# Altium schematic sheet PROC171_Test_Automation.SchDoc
size 431 x 279 mm; Date: Not shown in title block; ApprovedBy: Not shown in title block; CheckedBy: Not shown in title block; Author: Not shown in title block; CompanyName: Not shown in title block; Engineer: Not shown in title block; Organization: Not shown in title block; Address1: Not shown in title block; Address2: Not shown in title block; Address3: Not shown in title block; Address4: Not shown in title block; DocumentNumber: 14; Revision: Use project parameter SCH_Rev; SheetNumber: 14; SheetTotal: 26; PageSetup: Record=PageOptions¦CenterHorizontal=True¦CenterVertical=True¦PrintScale=1.00¦XCorrection=1.00¦YCorrection=1.00¦PrintKind=0¦BorderSize=5000000¦LeftOffset=0¦BottomOffset=0¦Orientation=2¦PaperLength=1000¦PaperWidth=1000¦Scale=100¦PaperSource=15¦PrintQuality=600¦MediaType=1¦DitherType=10¦PaperKind=Letter¦PrintScaleMode=1
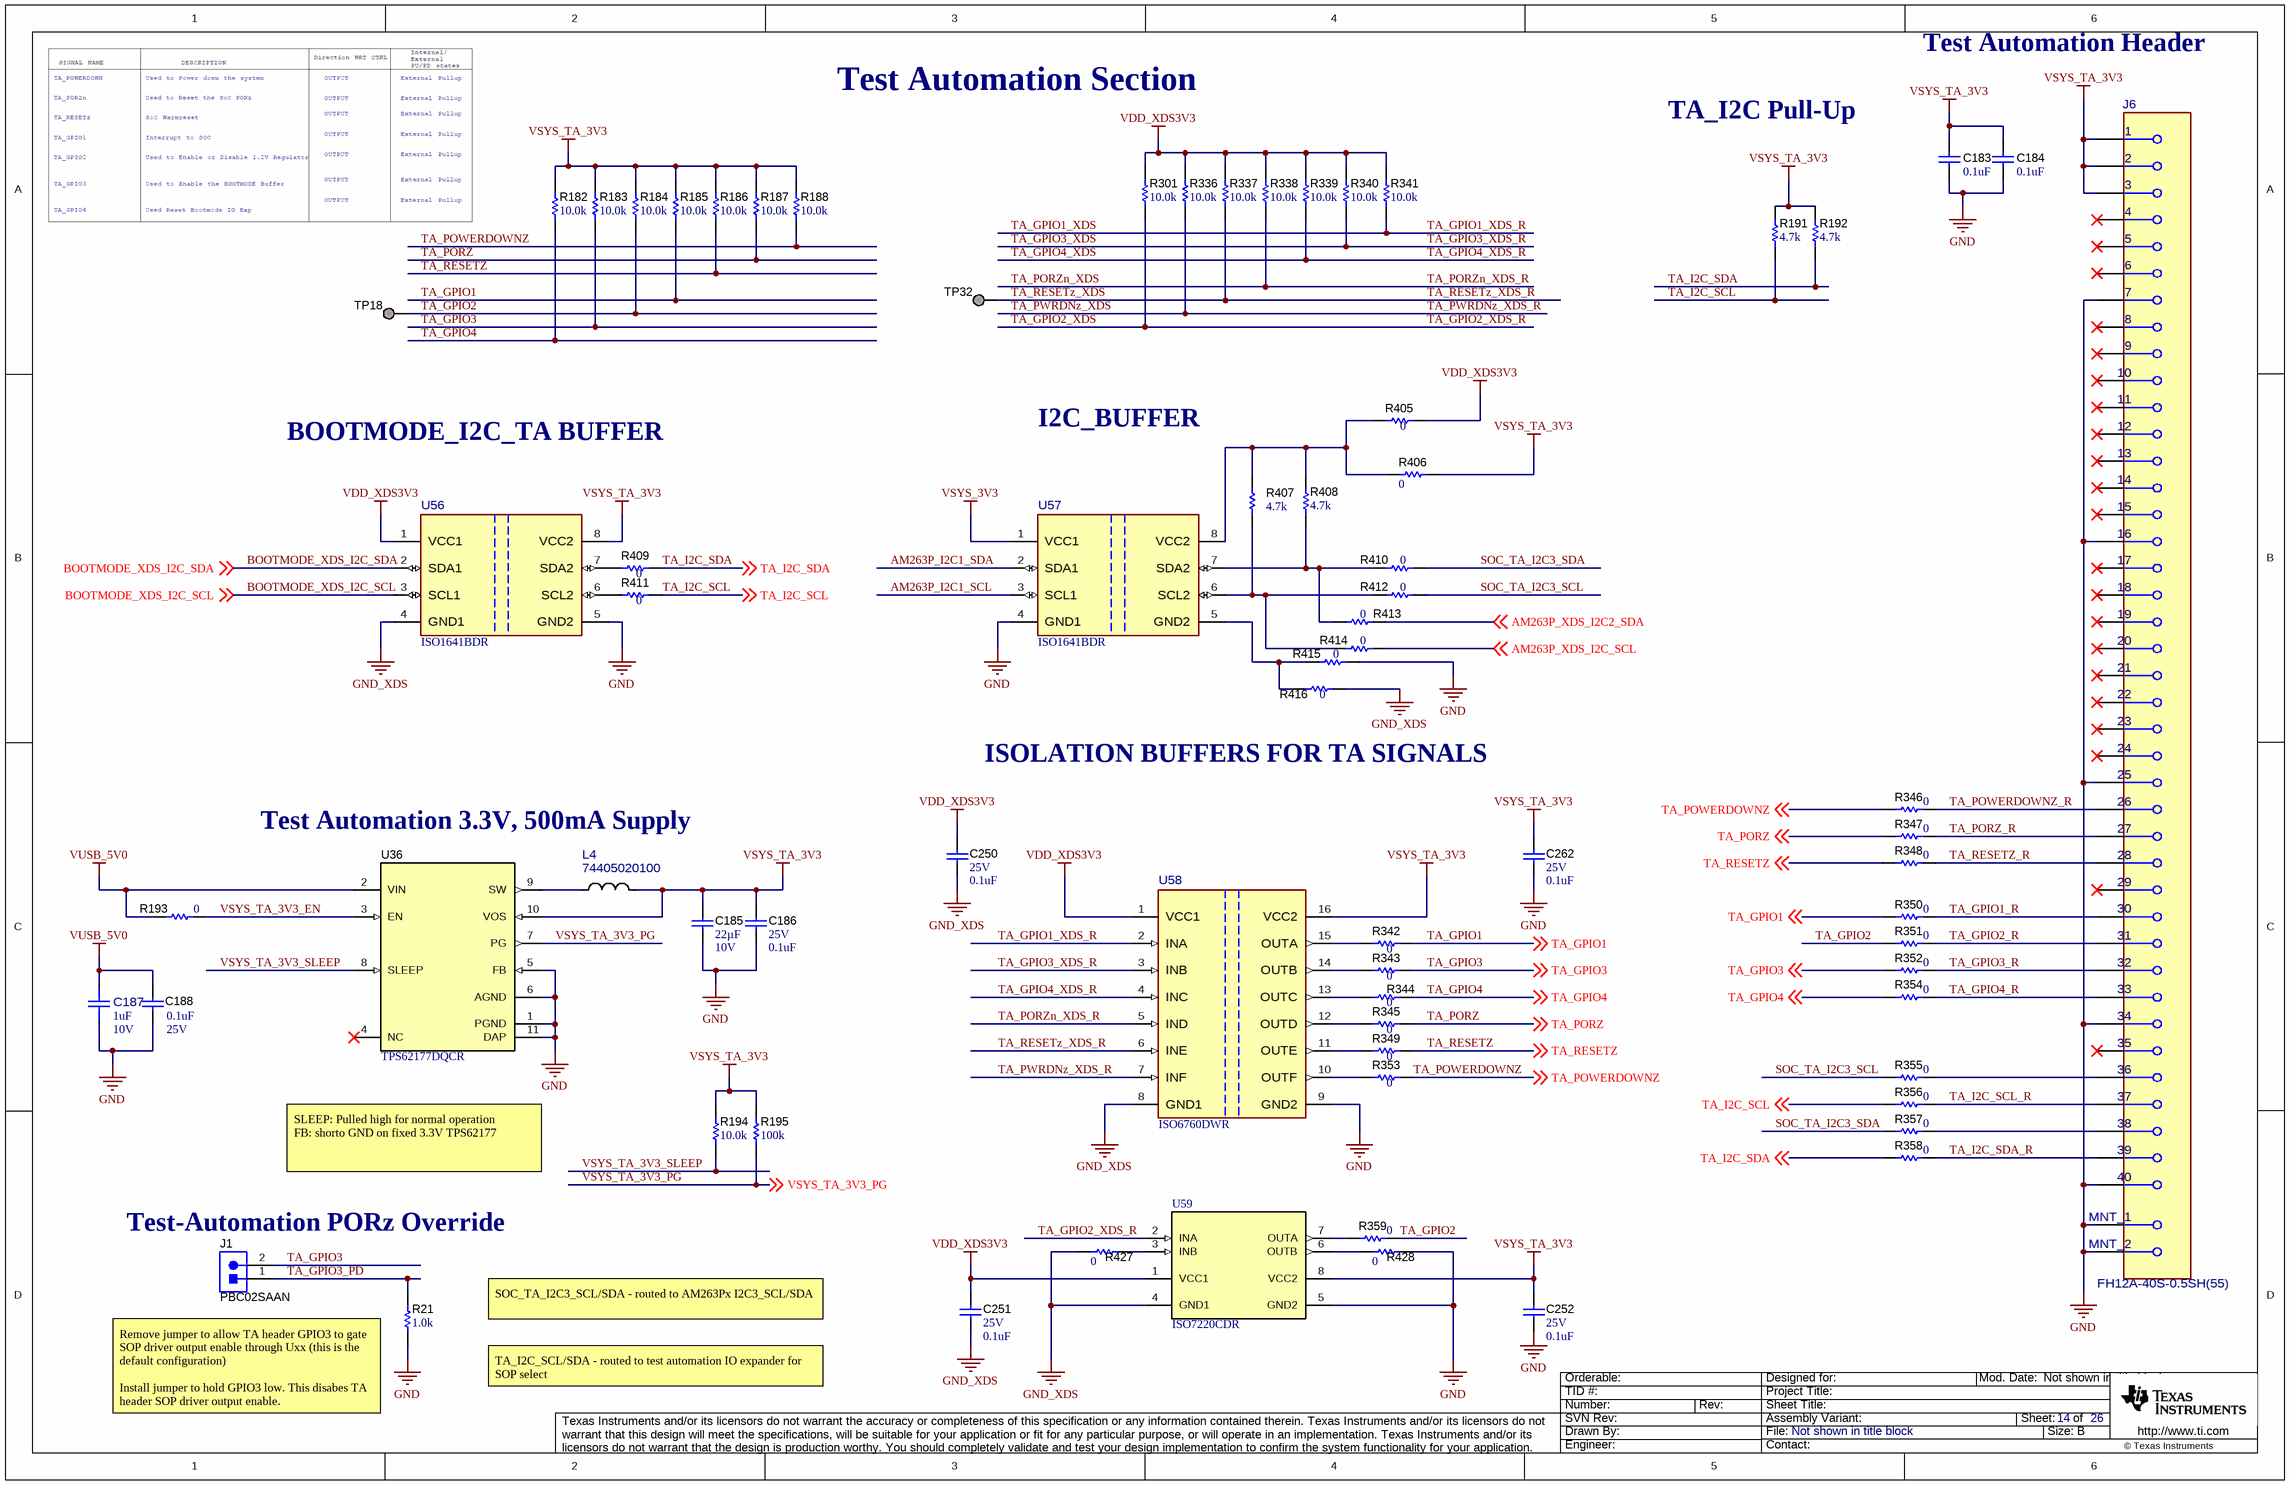
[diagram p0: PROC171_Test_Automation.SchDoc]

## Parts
C183  ValueDisplayed: 0.1uF  [0402]  (hidden comment: GRM155R71E104KE14D)
C184  ValueDisplayed: 0.1uF  [0402]  (hidden comment: GRM155R71E104KE14D)
C185  Cap_F: 22µF  VDC_V: 10V  [0805_HV]  (hidden comment: GRM21BZ71A226ME15L)
C186  VDC_V: 25V  ValueDisplayed: 0.1uF  [0402]  (hidden comment: GRM155R71E104KE14D)
C187  ValueDisplayed: 1uF  VDC_V: 10V  [FP-GRM155C71A105KE11D_0402-MFG]  (hidden comment: GRM155C71A105KE11D)
C188  VDC_V: 25V  ValueDisplayed: 0.1uF  [0402]  (hidden comment: GRM155R71E104KE14D)
C250  VDC_V: 25V  ValueDisplayed: 0.1uF  [0402]  (hidden comment: GRM155R71E104KE14D)
C251  VDC_V: 25V  ValueDisplayed: 0.1uF  [0402]  (hidden comment: GRM155R71E104KE14D)
C252  VDC_V: 25V  ValueDisplayed: 0.1uF  [0402]  (hidden comment: GRM155R71E104KE14D)
C262  VDC_V: 25V  ValueDisplayed: 0.1uF  [0402]  (hidden comment: GRM155R71E104KE14D)
J1  PBC02SAAN  [Sullins_PBC02SAAN]
J6  FH12A-40S-0.5SH(55)  [FP-FH12A-40S-0.5SH(55)_FFC40-MFG]
L4  74405020100  [FP-74405020100_SMT_IND_2MM0_1MM6-MFG]
R21  ValueDisplayed: 1.0k  [0402]  (hidden comment: ERJ-2GEJ102X)
R182  ValueDisplayed: 10.0k  [0402]  (hidden comment: ERJ-2RKF1002X)
R183  ValueDisplayed: 10.0k  [0402]  (hidden comment: ERJ-2RKF1002X)
R184  ValueDisplayed: 10.0k  [0402]  (hidden comment: ERJ-2RKF1002X)
R185  ValueDisplayed: 10.0k  [0402]  (hidden comment: ERJ-2RKF1002X)
R186  ValueDisplayed: 10.0k  [0402]  (hidden comment: ERJ-2RKF1002X)
R187  ValueDisplayed: 10.0k  [0402]  (hidden comment: ERJ-2RKF1002X)
R188  ValueDisplayed: 10.0k  [0402]  (hidden comment: ERJ-2RKF1002X)
R191  ValueDisplayed: 4.7k  [0402]  (hidden comment: CRCW04024K70JNED)
R192  ValueDisplayed: 4.7k  [0402]  (hidden comment: CRCW04024K70JNED)
R193  ValueDisplayed: 0  [0402L]  (hidden comment: ERJ-2GE0R00X)
R194  ValueDisplayed: 10.0k  [0402]  (hidden comment: ERJ-2RKF1002X)
R195  ValueDisplayed: 100k  [0402]  (hidden comment: ERJ-2RKF1003X)
R301  ValueDisplayed: 10.0k  [0402]  (hidden comment: ERJ-2RKF1002X)
R336  ValueDisplayed: 10.0k  [0402]  (hidden comment: ERJ-2RKF1002X)
R337  ValueDisplayed: 10.0k  [0402]  (hidden comment: ERJ-2RKF1002X)
R338  ValueDisplayed: 10.0k  [0402]  (hidden comment: ERJ-2RKF1002X)
R339  ValueDisplayed: 10.0k  [0402]  (hidden comment: ERJ-2RKF1002X)
R340  ValueDisplayed: 10.0k  [0402]  (hidden comment: ERJ-2RKF1002X)
R341  ValueDisplayed: 10.0k  [0402]  (hidden comment: ERJ-2RKF1002X)
R342  ValueDisplayed: 0  [0402]  (hidden comment: ERJ-2GE0R00X)
R343  ValueDisplayed: 0  [0402]  (hidden comment: ERJ-2GE0R00X)
R344  ValueDisplayed: 0  [0402]  (hidden comment: ERJ-2GE0R00X)
R345  ValueDisplayed: 0  [0402]  (hidden comment: ERJ-2GE0R00X)
R346  ValueDisplayed: 0  [0402]  (hidden comment: ERJ-2GE0R00X)
R347  ValueDisplayed: 0  [0402]  (hidden comment: ERJ-2GE0R00X)
R348  ValueDisplayed: 0  [0402]  (hidden comment: ERJ-2GE0R00X)
R349  ValueDisplayed: 0  [0402]  (hidden comment: ERJ-2GE0R00X)
R350  ValueDisplayed: 0  [0402]  (hidden comment: ERJ-2GE0R00X)
R351  ValueDisplayed: 0  [0402]  (hidden comment: ERJ-2GE0R00X)
R352  ValueDisplayed: 0  [0402]  (hidden comment: ERJ-2GE0R00X)
R353  ValueDisplayed: 0  [0402]  (hidden comment: ERJ-2GE0R00X)
R354  ValueDisplayed: 0  [0402]  (hidden comment: ERJ-2GE0R00X)
R355  ValueDisplayed: 0  [0402]  (hidden comment: ERJ-2GE0R00X)
R356  ValueDisplayed: 0  [0402]  (hidden comment: ERJ-2GE0R00X)
R357  ValueDisplayed: 0  [0402]  (hidden comment: ERJ-2GE0R00X)
R358  ValueDisplayed: 0  [0402]  (hidden comment: ERJ-2GE0R00X)
R359  ValueDisplayed: 0  [0402]  (hidden comment: ERJ-2GE0R00X)
R405  ValueDisplayed: 0  [0402]  (hidden comment: ERJ-2GE0R00X)
R406  ValueDisplayed: 0  [1210]  (hidden comment: CRCW12100000Z0EAHP)
R407  ValueDisplayed: 4.7k  [0402]  (hidden comment: CRCW04024K70JNED)
R408  ValueDisplayed: 4.7k  [0402]  (hidden comment: CRCW04024K70JNED)
R409  ValueDisplayed: 0  [0402]  (hidden comment: ERJ-2GE0R00X)
R410  ValueDisplayed: 0  [1210]  (hidden comment: CRCW12100000Z0EAHP)
R411  ValueDisplayed: 0  [0402]  (hidden comment: ERJ-2GE0R00X)
R412  ValueDisplayed: 0  [1210]  (hidden comment: CRCW12100000Z0EAHP)
R413  ValueDisplayed: 0  [0402]  (hidden comment: ERJ-2GE0R00X)
R414  ValueDisplayed: 0  [0402]  (hidden comment: ERJ-2GE0R00X)
R415  ValueDisplayed: 0  [1210]  (hidden comment: CRCW12100000Z0EAHP)
R416  ValueDisplayed: 0  [0402]  (hidden comment: ERJ-2GE0R00X)
R427  ValueDisplayed: 0  [0402]  (hidden comment: ERJ-2GE0R00X)
R428  ValueDisplayed: 0  [0402]  (hidden comment: ERJ-2GE0R00X)
TP18  TESTPOINT  [TP_25MIL-SMT]  (value not drawn)  (no BOM)
TP32  TESTPOINT  [TP_25MIL-SMT]  (value not drawn)  (no BOM)
U36  TPS62177DQCR  [DQC0010A]
U56  ISO1641BDR  [D0008A-MFG]
U57  ISO1641BDR  [D0008A-MFG]
U58  ISO6760DWR  [DW0016A-MFG]
U59  ISO7220CDR  [D0008B_N]

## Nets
GND: C183.1 C184.1 C185.2 C186.2 C187.1 C188.2 C252.2 C262.2 J6.7 J6.16 J6.25 J6.34 J6.40 J6.41(MNT_1) J6.42(MNT_2) R21.1 R415.2 R428.1 U36.1(PGND) U36.5(FB) U36.6(AGND) U36.11(DAP) U56.5(GND2) U57.4(GND1) U58.9(GND2) U59.5(GND2)
GND_XDS: C250.2 C251.2 R416.2 R427.2 U56.4(GND1) U58.8(GND1) U59.4(GND1)
VDD_XDS3V3: C250.1 C251.1 R301.1 R336.1 R337.1 R338.1 R339.1 R340.1 R341.1 R405.2 U56.1(VCC1) U58.1(VCC1) U59.1(VCC1)
VSYS_3V3: U57.1(VCC1)
VSYS_TA_3V3: C183.2 C184.2 C185.1 C186.1 C252.1 C262.1 J6.1 J6.2 J6.3 L4.2 R182.1 R183.1 R184.1 R185.1 R186.1 R187.1 R188.1 R191.2 R192.2 R194.2 R195.2 R406.2 U36.10(VOS) U56.8(VCC2) U58.16(VCC2) U59.8(VCC2)
VUSB_5V0: C187.2 C188.1 R193.2 U36.2(VIN)
AM263P_I2C1_SCL: U57.3(SCL1)
AM263P_I2C1_SDA: U57.2(SDA1)
AM263P_XDS_I2C2_SDA: R413.2 ; off-sheet AM263P_XDS_I2C2_SDA
AM263P_XDS_I2C_SCL: R414.2 ; off-sheet AM263P_XDS_I2C_SCL
BOOTMODE_XDS_I2C_SCL: U56.3(SCL1) ; off-sheet BOOTMODE_XDS_I2C_SCL
BOOTMODE_XDS_I2C_SDA: U56.2(SDA1) ; off-sheet BOOTMODE_XDS_I2C_SDA
SOC_TA_I2C3_SCL: R355.1 R412.2
SOC_TA_I2C3_SDA: R357.1 R410.2
TA_GPIO1: R185.2 R342.2 R350.1 ; off-sheet TA_GPIO1
TA_GPIO1_R: J6.30 R350.2
TA_GPIO1_XDS: R341.2 U58.2(INA)  [also labelled TA_GPIO1_XDS_R]
TA_GPIO2: R184.2 R351.1 R359.2 TP18.1
TA_GPIO2_R: J6.31 R351.2
TA_GPIO2_XDS: R301.2 U59.2(INA)  [also labelled TA_GPIO2_XDS_R]
TA_GPIO3: J1.2 R183.2 R343.2 R352.1 ; off-sheet TA_GPIO3
TA_GPIO3_PD: J1.1 R21.2
TA_GPIO3_R: J6.32 R352.2
TA_GPIO3_XDS: R340.2 U58.3(INB)  [also labelled TA_GPIO3_XDS_R]
TA_GPIO4: R182.2 R344.2 R354.1 ; off-sheet TA_GPIO4
TA_GPIO4_R: J6.33 R354.2
TA_GPIO4_XDS: R339.2 U58.4(INC)  [also labelled TA_GPIO4_XDS_R]
TA_I2C_SCL: R191.1 R356.1 R411.2 ; off-sheet TA_I2C_SCL
TA_I2C_SCL_R: J6.37 R356.2
TA_I2C_SDA: R192.1 R358.1 R409.2 ; off-sheet TA_I2C_SDA
TA_I2C_SDA_R: J6.39 R358.2
TA_PORZ: R187.2 R345.2 R347.1 ; off-sheet TA_PORZ
TA_PORZ_R: J6.27 R347.2
TA_PORZn_XDS: R338.2 U58.5(IND)  [also labelled TA_PORZn_XDS_R]
TA_POWERDOWNZ: R188.2 R346.1 R353.2 ; off-sheet TA_POWERDOWNZ
TA_POWERDOWNZ_R: J6.26 R346.2
TA_PWRDNz_XDS: R336.2 U58.7(INF)  [also labelled TA_PWRDNz_XDS_R]
TA_RESETZ: R186.2 R348.1 R349.2 ; off-sheet TA_RESETZ
TA_RESETZ_R: J6.28 R348.2
TA_RESETz_XDS: R337.2 TP32.1 U58.6(INE)  [also labelled TA_RESETz_XDS_R]
VSYS_TA_3V3_EN: R193.1 U36.3(EN)
VSYS_TA_3V3_PG: R195.1 U36.7(PG) ; off-sheet VSYS_TA_3V3_PG
VSYS_TA_3V3_SLEEP: R194.1 U36.8(SLEEP)
NetJ6_36: J6.36 R355.2
NetJ6_38: J6.38 R357.2
NetL4_1: L4.1 U36.9(SW)
NetR342_1: R342.1 U58.15(OUTA)
NetR343_1: R343.1 U58.14(OUTB)
NetR344_1: R344.1 U58.13(OUTC)
NetR345_1: R345.1 U58.12(OUTD)
NetR349_1: R349.1 U58.11(OUTE)
NetR353_1: R353.1 U58.10(OUTF)
NetR359_1: R359.1 U59.7(OUTA)
NetR405_1: R405.1 R406.1 R407.2 R408.2 U57.8(VCC2)
NetR407_1: R407.1 R412.1 R414.1 U57.6(SCL2)
NetR408_1: R408.1 R410.1 R413.1 U57.7(SDA2)
NetR409_1: R409.1 U56.7(SDA2)
NetR411_1: R411.1 U56.6(SCL2)
NetR415_1: R415.1 R416.1 U57.5(GND2)
NetR427_1: R427.1 U59.3(INB)
NetR428_2: R428.2 U59.6(OUTB)

Not connected (* = marked no-connect by the designer): J6 4* 5* 6* 8* 9* 10* 11* 12* 13* 14* 15* 17* 18* 19* 20* 21* 22* 23* 24* 29* 35*; U36 4(NC)*

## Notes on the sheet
- Test Automation Section
- Test Automation Header
- TA_I2C Pull-Up
- I2C_BUFFER
- BOOTMODE_I2C_TA BUFFER
- ISOLATION BUFFERS FOR TA SIGNALS
- Test Automation 3.3V, 500mA Supply
- SLEEP: Pulled high for normal operation
  FB: shorto GND on fixed 3.3V TPS62177
- (near J1) Test-Automation PORz Override
- SOC_TA_I2C3_SCL/SDA - routed to AM263Px I2C3_SCL/SDA
- Remove jumper to allow TA header GPIO3 to gate SOP driver output enable through Uxx (this is the default configuration)
  Install jumper to hold GPIO3 low. This disabes TA header SOP driver output enable.
- TA_I2C_SCL/SDA - routed to test automation IO expander for SOP select

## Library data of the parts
C183 C184 = CMP-0006659-2: CAP, CERM, 0.1 uF, 25 V, +/- 10%, X7R, 0402; Manufacturer: MuRata; TaMin_C: -55°C; Polarized: N; SizeAreaWB_mm2: 3; U/M: EA; Value: 0.1uF; TaMax_C: 125°C; SizeZ_mm: 0.6; SizeX_mm: 1; SizeY_mm: 0.5; Value2: 25V; Cap_F: 100nF; AEC Category: Q200; Value1: Unknown
C185 = CMP-0008377-2: CAP, CERM, 22 uF, 10 V, +/- 20%, X7R, 0805; Manufacturer: MuRata; SizeY_mm: 1.25; Cap_Case: 0805; SizeArea_mm2: 2.5; AEC Qualified: N; AEC Category: Q200; ValueDisplayed: 22uF; TaMin_C: -55°C; SizeAreaWB_mm2: 6.75; Value1: Unknown; U/M: EA; Value: 22uF; TaMax_C: 125°C; SizeZ_mm: 1.45; SizeX_mm: 2
C186 C188 C250-C252 C262 = CMP-0006659-2: CAP, CERM, 0.1 uF, 25 V, +/- 10%, X7R, 0402; Manufacturer: MuRata; TaMin_C: -55°C; Polarized: N; SizeAreaWB_mm2: 3; Value1: Unknown; U/M: EA; Value: 0.1uF; TaMax_C: 125°C; SizeZ_mm: 0.6; SizeX_mm: 1; SizeY_mm: 0.5; Cap_F: 100nF; AEC Category: Q200
C187 = CMP-0035346-1: 1µF ±10% 10V Ceramic Capacitor X7S 0402 (1005 Metric); Manufacturer: Murata; AEC Qualified: No; SizeZ_mm: 0.6mm; TempCo: 22%
J1 = CMP-0054566-1: Header, 100mil, 2x1, Gold, TH; Manufacturer: Sullins Connector Solutions; CNHeader: TRUE; Current_A: 3A; Green_Lifecycle: Active; Shrouded: N; Gender: Male; Green_REACh: Passed; Voltage_V: 1.8kV; Row_Count: 1; Pitch_mm: 2.54; CT: FALSE; Cert_UL: Y
J6 = CMP-0093156-1: Manufacturer: Hirose; Is Female: yes; ContactFinish: Gold,Nickel; Current_A: 500mA; DUT-Pitch_mm: 0.5mm; Voltage_V: 50V; SizeZ_mm: 3.6mm; Conn Gender: Female; Conn Orientation: Horizontal; AEC Qualified: No
L4 = CMP-0078538-1: 10µH Semi-Shielded Wirewound Inductor 580mA 816 mOhm Max Nonstandard; Manufacturer: Wurth Electronics; Symbol Name: SYM-74405020100; Material: Ferrite; SizeZ_mm: 1mm; Isat: 0.95A; AEC Qualified: No; Irms: 0.58A
R21 = CMP-0078193-1: RES, 1.0 k, 5%, 0.1 W, AEC-Q200 Grade 0, 0402; Manufacturer: Panasonic; Value_Code: 1k00; SizeArea_mm2: 0.5; AEC Qualified: Y; AEC Category: Q200; Res_ohm: 1k; Value: 1.0k; SizeZ_mm: 0.6; Green_REACh: Passed; EIA_Code: E24; TempCo: 200 ppm/C; AEC Grade: 0; Power_W: 100mW; VDC_V: 50V; Value2: 0.1W; Green_Lifecycle: Active; U/M: EA; SizeX_mm: 1
R182-R188 R194 R301 R336-R341 = CMP-0026658-1: RES, 10.0 k, 1%, 0.1 W, 0402; Manufacturer: Panasonic; Power_W: 100mW; TempCo: 100 ppm/C; Value_Code: 10k0; U/M: EA; Value: 10.0k; EIA_Code: E96; Res_ohm: 10k; SizeX_mm: 1; SizeY_mm: 0.5; SizeZ_mm: 0.6; Value2: 0.1W; VDC_V: 50V; AEC Category: Q200
R191 R192 R407 R408 = CMP-0026938-5: RES, 4.7 k, 5%, 0.063 W, AEC-Q200 Grade 0, 0402; Manufacturer: Vishay-Dale; Power_W: 63mW; TempCo: 200 ppm/C; Value_Code: 4k70; Value: 4.7k; EIA_Code: E24; SizeX_mm: 1; SizeY_mm: 0.5; SizeZ_mm: 0.6; Value2: 0.063W; AEC Qualified: Y; VDC_V: 50V; AEC Category: Q200; AEC Grade: 0
R193 R342-R359 R405 R409 R411 R413 R414 R416 R427 R428 = CMP-0026992-3: RES, 0, 5%, 0.1 W, AEC-Q200 Grade 0, 0402; Manufacturer: Panasonic; Power_W: 100mW; TempCo: 600 ppm/C; Value_Code: 0000; Value: 0; EIA_Code: E24; SizeX_mm: 1; SizeY_mm: 0.5; SizeZ_mm: 0.6; Value2: 0.1W; AEC Qualified: Y; VDC_V: 50V; AEC Category: Q200; SizeAreaWB_mm2: 3
R195 = CMP-0026659-2: RES, 100 k, 1%, 0.1 W, 0402; Manufacturer: Panasonic; U/M: EA; Value2: 0.1W; EIA_Code: E96; Value: 100k; SizeArea_mm2: 0.5; TempCo: 100 ppm/C; SizeZ_mm: 0.6; AEC Category: Q200; VDC_V: 50V; Power_W: 100mW; AEC Grade: 0; SizeX_mm: 1; AEC Qualified: Yes
R406 R410 R412 R415 = CMP-0015017-3: RES, 0, 1%, 0.75 W, AEC-Q200 Grade 0, 1210; Manufacturer: Vishay-Dale; Power_W: 750mW; TempCo: ppm/C; SizeAreaWB_mm2: 14.7; Value: 0; SizeX_mm: 3.2; SizeY_mm: 2.5; SizeZ_mm: 1.35; Value2: 0.75W; SizeArea_mm2: 8; AEC Qualified: Y; AEC Category: Q200
TP18 TP32 = CMP-0078143-3: TEST POINT.  No entry in BOM.
U36 = CMP-0067107-3: 28V, 0.5A Step-Down Converter with SNOOZE Mode, DQC0010A (WSON-10); Alternate PartNumber: TPS62177DQCT; Manufacturer: Texas Instruments; SizeZ_mm: 0.8; SizeX_mm: 2.0; SizeY_mm: 3.0; SizeArea_mm2: 6.0; CompType: IC; SizeAreaWB_mm2: 12.0
U56 U57 = CMP-0031336-1: Hot-swappable, robust-EMC bidirectional I2C isolator with unidirectional clock 8-SOIC -40 to 125; Manufacturer: Texas Instruments; SizeZ_mm: 1.75mm; AEC Qualified: No; Max Supply Voltage: 5.5V; Min Supply Voltage: 2.25V; Standoff Height: 0.11mm; TaMax_C: +125°C; TaMin_C: -40°C; TJmax_C: +150°C
U58 = CMP-0096103-1: General purpose, 50-Mbps, six-channel (6/0) digital isolator 16-SOIC -40 to 125; Manufacturer: Texas Instruments; AEC Qualified: No; Standoff Height: 0.1mm; Min Supply Voltage: 1.71V; TaMin_C: -40°C; TaMax_C: +125°C; TJmax_C: +150°C; Interface: LVCMOS; SizeZ_mm: 2.65mm; Max Supply Voltage: 5.5V
U59 = CMP-0029369-1: 25 Mbps Dual Channels, 2 / 0, Digital Isolator, 3.3 V / 5 V, -40 to +125 degC, 8-pin SOIC (D), Green (RoHS & no Sb/Br); Manufacturer: Texas Instruments; Supply Voltage(s)(V): 3.3, 5; Prop Delay(Max)(ns): 42; Insulation Rating(VRMS): 2500; Datarate(Mbps): 25; TTL/CMOS Input Threshold: TTL; Rating: Catalog; Input Noise Filter: Yes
